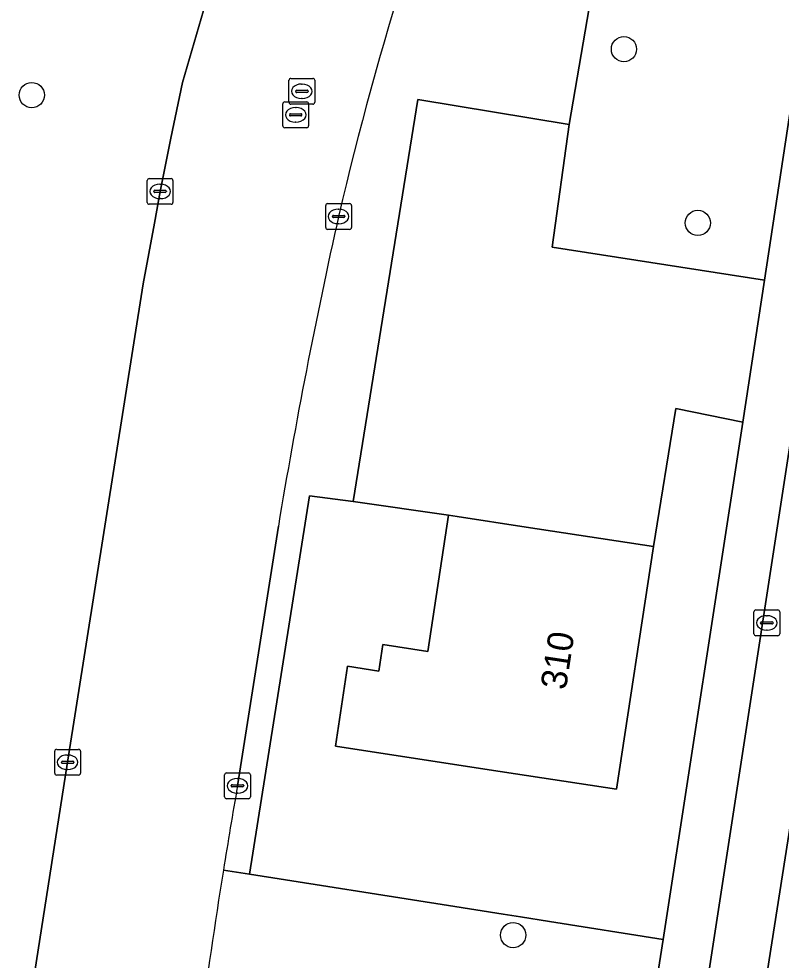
# Model space of a CAD drawing. Extents: x 161090 to 161692, y 379509 to 380907.
# Drawn here: x 161586.42 to 161615.99, y 380358.19 to 380394.7 of the extents above; entities that cross this region are included whole.
import ezdxf

# ---------------------------------------------------------------- set-up
doc = ezdxf.new("R2010")
doc.units = 0
for name, color, linetype in [('IMGEO_Berm_groen', 7, 'Continuous'), ('IMGEO_Boom', 7, 'Continuous'), ('IMGEO_Erf', 7, 'Continuous'), ('IMGEO_Fietspad_gesloten', 7, 'Continuous'), ('IMGEO_Groenvoorziening', 7, 'Continuous'), ('IMGEO_Kolk', 7, 'Continuous'), ('IMGEO_OVBaan_gesloten', 7, 'Continuous'), ('IMGEO_Pand', 7, 'Continuous'), ('IMGEO_Pand_nummerreeks', 7, 'Continuous'), ('IMGEO_Parkeervlak_open', 7, 'Continuous'), ('IMGEO_Rioolput', 7, 'Continuous'), ('IMGEO_Voetpad_open', 7, 'Continuous')]:
    doc.layers.add(name, color=color, linetype=linetype)

msp = doc.modelspace()

# ---------------------------------------------------------------- linework, layer by layer
at = {"layer": 'IMGEO_Berm_groen'}
for points in [[(161597.696, 380376.197), (161599.392, 380375.982), (161601.896, 380391.571), (161607.762, 380390.596), (161613.791, 380425.771), (161612.306, 380425.991)], [(161622.517, 380366.313), (161622.941, 380370.736), (161623.428, 380376.818), (161618.561, 380377.574), (161615.522, 380358.208), (161614.175, 380349.387), (161612.498, 380338.392), (161608.177, 380310.609)], [(161594.355, 380361.681), (161595.362, 380361.521), (161597.696, 380376.197)], [(161596.489, 380375.019), (161594.902, 380364.954)], [(161611.414, 380358.997), (161606.999, 380359.691), (161605.886, 380359.866), (161605.209, 380359.973), (161603.085, 380360.307), (161595.362, 380361.521), (161594.355, 380361.681)], [(161605.928, 380311.015), (161610.539, 380340.52), (161608.555, 380340.78), (161611.414, 380358.997)]]:
    msp.add_lwpolyline(points, dxfattribs=at)
for centre, radius, start, end in [((161724.132, 380357.942), 128.64, 157.92248, 166.90854), ((161805.867, 380340.551), 212.197, 167.33371, 170.65183), ((161833.983, 380323.315), 242.679, 170.1204, 170.90386), ((161822.075, 380325.281), 230.611, 170.91846, 174.05141)]:
    msp.add_arc(centre, radius, start, end, dxfattribs=at)
at = {"layer": 'IMGEO_Boom'}
for centre in [(161609.893, 380393.524), (161586.922, 380391.742), (161612.76, 380386.784), (161605.594, 380359.163)]:
    msp.add_circle(centre, 0.489, dxfattribs=at)
at = {"layer": 'IMGEO_Erf'}
msp.add_lwpolyline([(161603.087, 380375.446), (161599.392, 380375.982), (161597.696, 380376.197), (161595.362, 380361.521), (161603.085, 380360.307), (161605.209, 380359.973), (161605.886, 380359.866), (161606.999, 380359.691), (161611.414, 380358.997), (161614.501, 380379.058), (161611.904, 380379.584), (161611.039, 380374.237), (161609.609, 380364.827), (161604.666, 380365.578), (161598.703, 380366.485), (161599.175, 380369.59), (161600.385, 380369.406), (161600.541, 380370.428), (161602.284, 380370.163)], close=True, dxfattribs=at)
at = {"layer": 'IMGEO_Fietspad_gesloten'}
for points in [[(161608.177, 380310.609), (161612.498, 380338.392), (161614.175, 380349.387), (161615.522, 380358.208), (161618.561, 380377.574), (161619.001, 380380.379), (161619.636, 380384.663), (161619.668, 380384.881), (161622.43, 380403.035), (161622.852, 380405.923), (161625.07, 380420.051), (161625.649, 380423.882), (161627.147, 380433.8), (161627.322, 380434.961), (161629.991, 380452.28)], [(161623.371, 380423.923), (161622.87, 380420.7), (161611.943, 380349.647), (161610.562, 380340.668), (161610.539, 380340.52), (161605.928, 380311.015)]]:
    msp.add_lwpolyline(points, dxfattribs=at)
at = {"layer": 'IMGEO_Groenvoorziening'}
msp.add_lwpolyline([(161621.441, 380424.641), (161613.791, 380425.771), (161607.762, 380390.596), (161607.104, 380385.838), (161615.349, 380384.57)], close=True, dxfattribs=at)
msp.add_lwpolyline([(161586.42, 380353.783), (161588.314, 380365.868), (161591.244, 380384.418), (161591.689, 380386.776), (161591.9, 380388.006), (161592.319, 380390.065), (161592.775, 380392.226), (161594.304, 380397.524)], dxfattribs=at)
at = {"layer": 'IMGEO_Kolk'}
for p, q in [((161591.399, 380387.58), (161591.399, 380388.432)), ((161591.474, 380388.506), (161592.326, 380388.506)), ((161591.887, 380388.286), (161591.912, 380388.286)), ((161592.4, 380388.432), (161592.4, 380387.58)), ((161591.658, 380388), (161591.658, 380388.012)), ((161592.096, 380387.963), (161591.698, 380387.963)), ((161591.701, 380388.049), (161592.099, 380388.049)), ((161592.142, 380388.012), (161592.142, 380388)), ((161592.326, 380387.506), (161591.474, 380387.506)), ((161591.91, 380387.726), (161591.885, 380387.726)), ((161598.399, 380387.535), (161599.251, 380387.535)), ((161598.324, 380386.609), (161598.324, 380387.461)), ((161598.812, 380387.315), (161598.837, 380387.315)), ((161599.325, 380387.461), (161599.325, 380386.609)), ((161598.583, 380387.029), (161598.583, 380387.041)), ((161599.021, 380386.992), (161598.623, 380386.992)), ((161598.626, 380387.078), (161599.024, 380387.078)), ((161599.067, 380387.041), (161599.067, 380387.029)), ((161599.251, 380386.535), (161598.399, 380386.535)), ((161598.835, 380386.755), (161598.81, 380386.755)), ((161614.933, 380370.846), (161614.933, 380371.698)), ((161615.008, 380371.772), (161615.86, 380371.772)), ((161615.421, 380371.552), (161615.446, 380371.552)), ((161615.934, 380371.698), (161615.934, 380370.846)), ((161615.192, 380371.266), (161615.192, 380371.278)), ((161615.63, 380371.229), (161615.232, 380371.229)), ((161615.235, 380371.315), (161615.633, 380371.315)), ((161615.676, 380371.278), (161615.676, 380371.266)), ((161615.86, 380370.772), (161615.008, 380370.772)), ((161615.444, 380370.992), (161615.419, 380370.992)), ((161587.888, 380366.368), (161588.74, 380366.368)), ((161587.813, 380365.442), (161587.813, 380366.294)), ((161588.301, 380366.148), (161588.326, 380366.148)), ((161588.814, 380366.294), (161588.814, 380365.442)), ((161588.072, 380365.862), (161588.072, 380365.874)), ((161588.51, 380365.825), (161588.112, 380365.825)), ((161588.115, 380365.911), (161588.513, 380365.911)), ((161588.556, 380365.874), (161588.556, 380365.862)), ((161588.74, 380365.368), (161587.888, 380365.368)), ((161588.324, 380365.588), (161588.299, 380365.588)), ((161594.401, 380364.528), (161594.401, 380365.38)), ((161594.476, 380365.454), (161595.328, 380365.454)), ((161594.889, 380365.234), (161594.914, 380365.234)), ((161595.402, 380365.38), (161595.402, 380364.528)), ((161594.66, 380364.948), (161594.66, 380364.96)), ((161595.098, 380364.911), (161594.7, 380364.911)), ((161594.703, 380364.997), (161595.101, 380364.997)), ((161595.144, 380364.96), (161595.144, 380364.948)), ((161594.912, 380364.674), (161594.887, 380364.674)), ((161595.328, 380364.454), (161594.476, 380364.454))]:
    msp.add_line(p, q, dxfattribs=at)
for points in [[(161591.399, 380387.58), (161591.399, 380388.432)], [(161591.474, 380388.506), (161592.326, 380388.506)], [(161592.4, 380388.432), (161592.4, 380387.58)], [(161592.326, 380387.506), (161591.474, 380387.506)], [(161598.399, 380387.535), (161599.251, 380387.535)], [(161598.324, 380386.609), (161598.324, 380387.461)], [(161599.325, 380387.461), (161599.325, 380386.609)], [(161599.251, 380386.535), (161598.399, 380386.535)], [(161614.933, 380370.846), (161614.933, 380371.698)], [(161615.008, 380371.772), (161615.86, 380371.772)], [(161615.934, 380371.698), (161615.934, 380370.846)], [(161615.86, 380370.772), (161615.008, 380370.772)], [(161587.888, 380366.368), (161588.74, 380366.368)], [(161587.813, 380365.442), (161587.813, 380366.294)], [(161588.814, 380366.294), (161588.814, 380365.442)], [(161588.74, 380365.368), (161587.888, 380365.368)], [(161594.401, 380364.528), (161594.401, 380365.38)], [(161594.476, 380365.454), (161595.328, 380365.454)], [(161595.402, 380365.38), (161595.402, 380364.528)], [(161595.328, 380364.454), (161594.476, 380364.454)]]:
    msp.add_lwpolyline(points, dxfattribs=at)
for centre, radius, start, end in [((161591.476, 380388.43), 0.0765, 91.552, 178.448), ((161591.476, 380388.43), 0.0765, 91.552, 178.448), ((161592.324, 380388.43), 0.0765, 1.552, 88.448), ((161592.324, 380388.43), 0.0765, 1.552, 88.448), ((161591.698, 380388.009), 0.0403, 85.8775, 175.7526), ((161591.695, 380387.999), 0.0366, 178.938, 274.7102), ((161592.099, 380388.006), 0.043, 264.8664, 352.4533), ((161592.103, 380388.011), 0.0386, 1.7309, 96.639), ((161591.476, 380387.582), 0.0765, 181.552, 268.448), ((161591.476, 380387.582), 0.0765, 181.552, 268.448), ((161592.324, 380387.582), 0.0765, 271.552, 358.448), ((161592.324, 380387.582), 0.0765, 271.552, 358.448), ((161598.401, 380387.459), 0.0765, 91.552, 178.448), ((161598.401, 380387.459), 0.0765, 91.552, 178.448), ((161599.249, 380387.459), 0.0765, 1.552, 88.448), ((161599.249, 380387.459), 0.0765, 1.552, 88.448), ((161598.623, 380387.038), 0.0403, 85.8775, 175.7526), ((161598.62, 380387.028), 0.0366, 178.938, 274.7102), ((161599.024, 380387.035), 0.043, 264.8664, 352.4533), ((161599.028, 380387.04), 0.0386, 1.7309, 96.639), ((161598.401, 380386.611), 0.0765, 181.552, 268.448), ((161598.401, 380386.611), 0.0765, 181.552, 268.448), ((161599.249, 380386.611), 0.0765, 271.552, 358.448), ((161599.249, 380386.611), 0.0765, 271.552, 358.448), ((161615.01, 380371.696), 0.0765, 91.552, 178.448), ((161615.01, 380371.696), 0.0765, 91.552, 178.448), ((161615.858, 380371.696), 0.0765, 1.552, 88.448), ((161615.858, 380371.696), 0.0765, 1.552, 88.448), ((161615.232, 380371.275), 0.0403, 85.8775, 175.7526), ((161615.229, 380371.265), 0.0366, 178.938, 274.7102), ((161615.633, 380371.272), 0.043, 264.8664, 352.4533), ((161615.637, 380371.277), 0.0386, 1.7309, 96.639), ((161615.01, 380370.848), 0.0765, 181.552, 268.448), ((161615.01, 380370.848), 0.0765, 181.552, 268.448), ((161615.858, 380370.848), 0.0765, 271.552, 358.448), ((161615.858, 380370.848), 0.0765, 271.552, 358.448), ((161587.89, 380366.292), 0.0765, 91.552, 178.448), ((161587.89, 380366.292), 0.0765, 91.552, 178.448), ((161588.738, 380366.292), 0.0765, 1.552, 88.448), ((161588.738, 380366.292), 0.0765, 1.552, 88.448), ((161588.112, 380365.871), 0.0403, 85.8775, 175.7526), ((161588.109, 380365.861), 0.0366, 178.938, 274.7102), ((161588.513, 380365.868), 0.043, 264.8664, 352.4533), ((161588.517, 380365.873), 0.0386, 1.7309, 96.639), ((161587.89, 380365.444), 0.0765, 181.552, 268.448), ((161587.89, 380365.444), 0.0765, 181.552, 268.448), ((161588.738, 380365.444), 0.0765, 271.552, 358.448), ((161588.738, 380365.444), 0.0765, 271.552, 358.448), ((161594.478, 380365.378), 0.0765, 91.552, 178.448), ((161594.478, 380365.378), 0.0765, 91.552, 178.448), ((161595.326, 380365.378), 0.0765, 1.552, 88.448), ((161595.326, 380365.378), 0.0765, 1.552, 88.448), ((161594.7, 380364.957), 0.0403, 85.8775, 175.7526), ((161594.697, 380364.947), 0.0366, 178.938, 274.7102), ((161595.101, 380364.954), 0.043, 264.8664, 352.4533), ((161595.105, 380364.959), 0.0386, 1.7309, 96.639), ((161594.478, 380364.53), 0.0765, 181.552, 268.448), ((161594.478, 380364.53), 0.0765, 181.552, 268.448), ((161595.326, 380364.53), 0.0765, 271.552, 358.448), ((161595.326, 380364.53), 0.0765, 271.552, 358.448)]:
    msp.add_arc(centre, radius, start, end, dxfattribs=at)
for centre, major_axis, ratio, start_param, end_param in [((161591.886, 380388.006), (-0.387, 0.002), 0.722429, 4.712389, 7.853982), ((161591.911, 380388.006), (-0.39, 0.002), 0.717154, 1.570796, 4.712389), ((161598.811, 380387.035), (-0.387, 0.002), 0.722429, 4.712389, 7.853982), ((161598.836, 380387.035), (-0.39, 0.002), 0.717154, 1.570796, 4.712389), ((161615.42, 380371.272), (-0.387, 0.002), 0.722429, 4.712389, 7.853982), ((161615.445, 380371.272), (-0.39, 0.002), 0.717154, 1.570796, 4.712389), ((161588.3, 380365.868), (-0.387, 0.002), 0.722429, 4.712389, 7.853982), ((161588.325, 380365.868), (-0.39, 0.002), 0.717154, 1.570796, 4.712389), ((161594.888, 380364.954), (-0.387, 0.002), 0.722429, 4.712389, 7.853982), ((161594.913, 380364.954), (-0.39, 0.002), 0.717154, 1.570796, 4.712389)]:
    msp.add_ellipse(centre, major_axis=major_axis, ratio=ratio, start_param=start_param, end_param=end_param, dxfattribs=at)
at = {"layer": 'IMGEO_OVBaan_gesloten'}
for points in [[(161594.304, 380397.524), (161592.775, 380392.226), (161592.319, 380390.065), (161591.9, 380388.006), (161591.689, 380386.776), (161591.244, 380384.418), (161588.314, 380365.868), (161586.42, 380353.783)], [(161594.902, 380364.954), (161596.489, 380375.019)]]:
    msp.add_lwpolyline(points, dxfattribs=at)
for centre, radius, start, end in [((161724.132, 380357.942), 128.64, 157.92248, 166.90854), ((161805.867, 380340.551), 212.197, 167.33371, 170.65183), ((161833.983, 380323.315), 242.679, 170.1204, 170.90386), ((161822.075, 380325.281), 230.611, 170.91846, 174.05141)]:
    msp.add_arc(centre, radius, start, end, dxfattribs=at)
at = {"layer": 'IMGEO_Pand'}
msp.add_lwpolyline([(161606.096, 380374.989), (161603.426, 380375.395), (161603.087, 380375.446), (161602.284, 380370.163), (161600.541, 380370.428), (161600.385, 380369.406), (161599.175, 380369.59), (161598.703, 380366.485), (161604.666, 380365.578), (161609.609, 380364.827), (161611.039, 380374.237)], close=True, dxfattribs=at)
at = {"layer": 'IMGEO_Parkeervlak_open'}
msp.add_lwpolyline([(161615.349, 380384.57), (161607.104, 380385.838), (161607.762, 380390.596), (161601.896, 380391.571), (161599.392, 380375.982), (161603.087, 380375.446), (161603.426, 380375.395), (161606.096, 380374.989), (161611.039, 380374.237), (161611.904, 380379.584), (161614.501, 380379.058)], close=True, dxfattribs=at)
at = {"layer": 'IMGEO_Rioolput'}
for p, q in [((161596.9, 380391.463), (161596.9, 380392.315)), ((161596.975, 380392.389), (161597.827, 380392.389)), ((161597.901, 380392.315), (161597.901, 380391.463)), ((161597.159, 380391.883), (161597.159, 380391.895)), ((161597.202, 380391.932), (161597.6, 380391.932)), ((161597.388, 380392.169), (161597.413, 380392.169)), ((161597.643, 380391.895), (161597.643, 380391.883)), ((161597.597, 380391.846), (161597.199, 380391.846)), ((161597.411, 380391.609), (161597.386, 380391.609)), ((161596.659, 380390.55), (161596.659, 380391.402)), ((161596.734, 380391.476), (161597.586, 380391.476)), ((161597.827, 380391.389), (161596.975, 380391.389)), ((161597.147, 380391.256), (161597.172, 380391.256)), ((161597.66, 380391.402), (161597.66, 380390.55)), ((161596.918, 380390.97), (161596.918, 380390.982)), ((161597.356, 380390.933), (161596.958, 380390.933)), ((161596.961, 380391.019), (161597.359, 380391.019)), ((161597.402, 380390.982), (161597.402, 380390.97)), ((161597.586, 380390.476), (161596.734, 380390.476)), ((161597.17, 380390.696), (161597.145, 380390.696))]:
    msp.add_line(p, q, dxfattribs=at)
for points in [[(161596.9, 380391.463), (161596.9, 380392.315)], [(161596.975, 380392.389), (161597.827, 380392.389)], [(161597.901, 380392.315), (161597.901, 380391.463)], [(161596.659, 380390.55), (161596.659, 380391.402)], [(161596.734, 380391.476), (161597.586, 380391.476)], [(161597.827, 380391.389), (161596.975, 380391.389)], [(161597.66, 380391.402), (161597.66, 380390.55)], [(161597.586, 380390.476), (161596.734, 380390.476)]]:
    msp.add_lwpolyline(points, dxfattribs=at)
for centre, radius, start, end in [((161596.977, 380392.313), 0.0765, 91.552, 178.448), ((161596.977, 380392.313), 0.0765, 91.552, 178.448), ((161597.825, 380392.313), 0.0765, 1.552, 88.448), ((161597.825, 380392.313), 0.0765, 1.552, 88.448), ((161597.199, 380391.892), 0.0403, 85.8775, 175.7526), ((161597.196, 380391.882), 0.0366, 178.938, 274.7102), ((161597.6, 380391.889), 0.043, 264.8664, 352.4533), ((161597.604, 380391.894), 0.0386, 1.7309, 96.639), ((161596.736, 380391.4), 0.0765, 91.552, 178.448), ((161596.736, 380391.4), 0.0765, 91.552, 178.448), ((161596.977, 380391.465), 0.0765, 181.552, 268.448), ((161596.977, 380391.465), 0.0765, 181.552, 268.448), ((161597.584, 380391.4), 0.0765, 1.552, 88.448), ((161597.584, 380391.4), 0.0765, 1.552, 88.448), ((161597.825, 380391.465), 0.0765, 271.552, 358.448), ((161597.825, 380391.465), 0.0765, 271.552, 358.448), ((161596.958, 380390.979), 0.0403, 85.8775, 175.7526), ((161596.955, 380390.969), 0.0366, 178.938, 274.7102), ((161597.359, 380390.976), 0.043, 264.8664, 352.4533), ((161597.363, 380390.981), 0.0386, 1.7309, 96.639), ((161596.736, 380390.552), 0.0765, 181.552, 268.448), ((161596.736, 380390.552), 0.0765, 181.552, 268.448), ((161597.584, 380390.552), 0.0765, 271.552, 358.448), ((161597.584, 380390.552), 0.0765, 271.552, 358.448)]:
    msp.add_arc(centre, radius, start, end, dxfattribs=at)
for centre, major_axis, ratio, start_param, end_param in [((161597.387, 380391.889), (-0.387, 0.002), 0.722429, 4.712389, 7.853982), ((161597.412, 380391.889), (-0.39, 0.002), 0.717154, 1.570796, 4.712389), ((161597.146, 380390.976), (-0.387, 0.002), 0.722429, 4.712389, 7.853982), ((161597.171, 380390.976), (-0.39, 0.002), 0.717154, 1.570796, 4.712389)]:
    msp.add_ellipse(centre, major_axis=major_axis, ratio=ratio, start_param=start_param, end_param=end_param, dxfattribs=at)
at = {"layer": 'IMGEO_Voetpad_open'}
msp.add_lwpolyline([(161621.991, 380428.256), (161621.441, 380424.641), (161615.349, 380384.57), (161614.501, 380379.058), (161611.414, 380358.997), (161608.555, 380340.78), (161610.539, 380340.52), (161610.562, 380340.668), (161611.943, 380349.647), (161622.87, 380420.7)], dxfattribs=at)

# ---------------------------------------------------------------- texts
at = {"layer": 'IMGEO_Pand_nummerreeks'}
msp.add_text('310', height=1, rotation=81.3591, dxfattribs=at).set_placement((161607.64, 380368.642))

doc.saveas('drawing.dxf')
